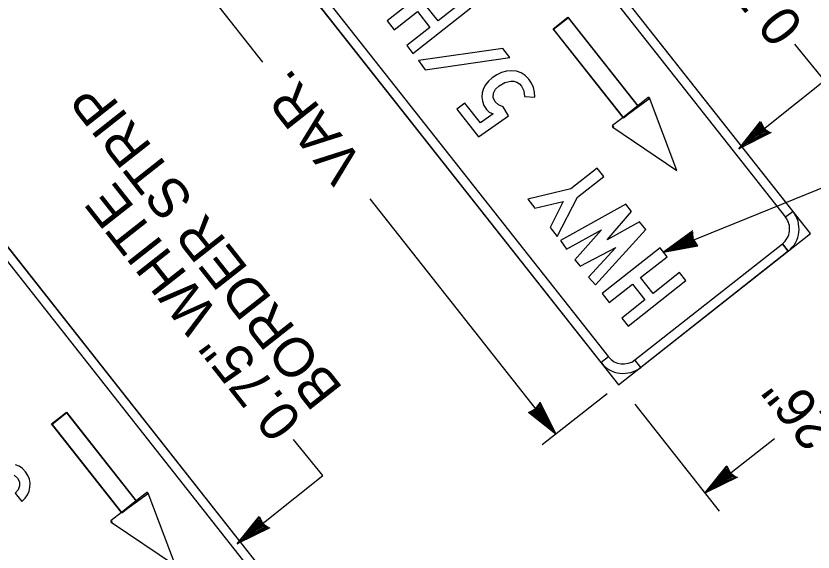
# Model space of a CAD drawing. Extents: x 672239 to 673995, y 1673540 to 1675195.
# Drawn here: x 672425.9 to 672510.8, y 1674938.1 to 1674995.2 of the extents above; entities that cross this region are included whole.
import ezdxf

# ---------------------------------------------------------------- set-up
doc = ezdxf.new("R2010")
doc.units = 0
doc.layers.add('C-ALGN-SYMB', color=7, linetype='Continuous')
doc.layers.add('C-ANNO-SYMB', color=7, linetype='Continuous')

msp = doc.modelspace()

# ---------------------------------------------------------------- linework, layer by layer
at = {"layer": 'C-ALGN-SYMB'}
for p, q in [((672452.225, 1674990.264), (672431.41, 1675016.666)), ((672502.851, 1674981.07), (672505.171, 1674983.98)), ((672503.069, 1674981.306), (672505.153, 1674983.832)), ((672503.42, 1674981.582), (672505.15, 1674983.663)), ((672503.639, 1674981.682), (672505.193, 1674983.398)), ((672503.71, 1674981.806), (672505.152, 1674983.532)), ((672505.15, 1674983.663), (672505.288, 1674983.403)), ((672505.152, 1674983.532), (672505.833, 1674982.834)), ((672505.153, 1674983.832), (672505.494, 1674983.267)), ((672505.171, 1674983.98), (672505.564, 1674983.221)), ((672505.193, 1674983.398), (672505.654, 1674982.892)), ((672505.288, 1674983.403), (672505.833, 1674982.834)), ((672506.312, 1674982.776), (672502.851, 1674981.07)), ((672505.954, 1674982.762), (672503.111, 1674981.338)), ((672506.12, 1674982.723), (672503.272, 1674981.43)), ((672505.833, 1674982.834), (672503.639, 1674981.682)), ((672505.833, 1674982.834), (672503.71, 1674981.806)), ((672504.144, 1674982.145), (672505.138, 1674983.254)), ((672505.654, 1674982.892), (672504.144, 1674982.145)), ((672504.531, 1674982.414), (672505.103, 1674983.127)), ((672505.491, 1674982.932), (672504.531, 1674982.414)), ((672505.196, 1674983.266), (672504.691, 1674982.508)), ((672504.867, 1674982.71), (672505.133, 1674983.05)), ((672505.384, 1674982.981), (672504.867, 1674982.71)), ((672505.103, 1674983.127), (672505.384, 1674982.981)), ((672505.133, 1674983.05), (672505.215, 1674982.985)), ((672505.138, 1674983.254), (672505.491, 1674982.932)), ((672505.572, 1674982.996), (672505.196, 1674983.266)), ((672505.215, 1674982.985), (672505.572, 1674982.996)), ((672505.494, 1674983.267), (672506.165, 1674982.794)), ((672505.564, 1674983.221), (672505.805, 1674982.911)), ((672505.805, 1674982.911), (672506.12, 1674982.723)), ((672506.165, 1674982.794), (672505.946, 1674982.857)), ((672505.946, 1674982.857), (672505.954, 1674982.762)), ((672504.691, 1674982.508), (672504.437, 1674982.407)), ((672483.386, 1674950.667), (672463.624, 1674975.735)), ((672497.974, 1674972.305), (672494.854, 1674970.035)), ((672497.795, 1674971.995), (672495.212, 1674970.141)), ((672497.838, 1674972.159), (672495.368, 1674970.24)), ((672497.802, 1674971.854), (672495.762, 1674970.448)), ((672497.802, 1674971.854), (672495.905, 1674970.454)), ((672497.771, 1674971.668), (672496.407, 1674970.68)), ((672497.648, 1674971.237), (672497.824, 1674971.548)), ((672498.004, 1674971.025), (672497.771, 1674971.668)), ((672497.875, 1674971.943), (672497.795, 1674971.995)), ((672498.053, 1674971.107), (672497.802, 1674971.854)), ((672498.103, 1674970.926), (672497.802, 1674971.854)), ((672497.824, 1674971.548), (672497.889, 1674971.089)), ((672497.858, 1674971.793), (672497.838, 1674972.159)), ((672498.02, 1674971.435), (672497.858, 1674971.793)), ((672497.921, 1674972.166), (672497.875, 1674971.943)), ((672498.028, 1674971.353), (672497.921, 1674972.166)), ((672494.854, 1674970.035), (672498.509, 1674970.735)), ((672495.164, 1674970.118), (672498.369, 1674970.788)), ((672495.334, 1674970.31), (672496.083, 1674970.82)), ((672495.572, 1674970.301), (672498.219, 1674970.864)), ((672496.083, 1674970.82), (672495.572, 1674970.301)), ((672495.762, 1674970.448), (672498.004, 1674971.025)), ((672495.905, 1674970.454), (672498.103, 1674970.926)), ((672496.299, 1674970.659), (672496.686, 1674970.948)), ((672496.776, 1674970.817), (672496.299, 1674970.659)), ((672496.407, 1674970.68), (672497.851, 1674971.043)), ((672496.983, 1674970.994), (672496.776, 1674970.817)), ((672497.73, 1674971.506), (672496.825, 1674970.897)), ((672496.825, 1674970.897), (672497.722, 1674971.071)), ((672497.889, 1674971.089), (672496.983, 1674970.994)), ((672497.724, 1674971.388), (672497.243, 1674971.056)), ((672497.243, 1674971.056), (672497.668, 1674971.134)), ((672497.668, 1674971.134), (672497.648, 1674971.237)), ((672497.722, 1674971.071), (672497.724, 1674971.388)), ((672497.851, 1674971.043), (672497.73, 1674971.506)), ((672498.509, 1674970.735), (672498.02, 1674971.435)), ((672498.369, 1674970.788), (672498.028, 1674971.353)), ((672498.219, 1674970.864), (672498.053, 1674971.107)), ((672495.368, 1674970.24), (672495.164, 1674970.118)), ((672495.212, 1674970.141), (672495.334, 1674970.31)), ((672488.846, 1674954.972), (672481.942, 1674949.529)), ((672481.191, 1674953.311), (672481.664, 1674953.982)), ((672481.547, 1674953.622), (672481.735, 1674953.937)), ((672481.664, 1674953.982), (672481.601, 1674953.763)), ((672481.601, 1674953.763), (672481.696, 1674953.771)), ((672481.682, 1674954.129), (672483.386, 1674950.667)), ((672481.696, 1674953.771), (672483.118, 1674950.927)), ((672481.735, 1674953.937), (672483.026, 1674951.088)), ((672491.789, 1674953.846), (672500.745, 1674942.486)), ((672480.477, 1674952.989), (672481.237, 1674953.381)), ((672483.386, 1674950.667), (672480.477, 1674952.989)), ((672480.626, 1674952.97), (672481.191, 1674953.311)), ((672483.15, 1674950.885), (672480.626, 1674952.97)), ((672480.794, 1674952.968), (672481.054, 1674953.106)), ((672482.874, 1674951.236), (672480.794, 1674952.968)), ((672480.926, 1674952.969), (672481.624, 1674953.65)), ((672482.651, 1674951.527), (672480.926, 1674952.969)), ((672481.054, 1674953.106), (672481.624, 1674953.65)), ((672481.06, 1674953.011), (672481.566, 1674953.471)), ((672482.775, 1674951.455), (672481.06, 1674953.011)), ((672481.462, 1674953.389), (672481.191, 1674953.014)), ((672481.191, 1674953.014), (672481.949, 1674952.508)), ((672481.204, 1674952.955), (672481.526, 1674953.308)), ((672482.312, 1674951.961), (672481.204, 1674952.955)), ((672481.237, 1674953.381), (672481.547, 1674953.622)), ((672481.331, 1674952.92), (672481.477, 1674953.201)), ((672482.043, 1674952.348), (672481.331, 1674952.92)), ((672481.408, 1674952.95), (672481.473, 1674953.032)), ((672481.747, 1674952.684), (672481.408, 1674952.95)), ((672481.473, 1674953.032), (672481.462, 1674953.389)), ((672481.477, 1674953.201), (672481.747, 1674952.684)), ((672481.526, 1674953.308), (672482.043, 1674952.348)), ((672481.566, 1674953.471), (672482.312, 1674951.961)), ((672481.624, 1674953.65), (672482.651, 1674951.527)), ((672481.624, 1674953.65), (672482.775, 1674951.455)), ((672481.949, 1674952.508), (672482.05, 1674952.254)), ((672482.05, 1674952.254), (672482.397, 1674951.893)), ((672482.397, 1674951.893), (672482.19, 1674952.328)), ((672483.089, 1674951.135), (672482.664, 1674951.934)), ((672482.664, 1674951.934), (672482.874, 1674951.236)), ((672483.026, 1674951.088), (672483.15, 1674950.885)), ((672483.118, 1674950.927), (672483.089, 1674951.135)), ((672499.25, 1674944.382), (672506.639, 1674950.206)), ((672499.25, 1674944.382), (672501.572, 1674947.29)), ((672499.468, 1674944.618), (672501.554, 1674947.142)), ((672499.82, 1674944.893), (672501.551, 1674946.973)), ((672501.551, 1674946.973), (672501.689, 1674946.713)), ((672501.554, 1674947.142), (672501.894, 1674946.576)), ((672501.572, 1674947.29), (672501.964, 1674946.531)), ((672502.712, 1674946.085), (672499.25, 1674944.382)), ((672500.038, 1674944.993), (672501.594, 1674946.708)), ((672502.233, 1674946.143), (672500.038, 1674944.993)), ((672500.11, 1674945.117), (672501.552, 1674946.842)), ((672502.233, 1674946.143), (672500.11, 1674945.117)), ((672500.544, 1674945.456), (672501.538, 1674946.564)), ((672502.054, 1674946.202), (672500.544, 1674945.456)), ((672500.931, 1674945.725), (672501.503, 1674946.437)), ((672501.891, 1674946.242), (672500.931, 1674945.725)), ((672501.597, 1674946.576), (672501.091, 1674945.818)), ((672501.267, 1674946.02), (672501.533, 1674946.36)), ((672501.784, 1674946.291), (672501.267, 1674946.02)), ((672501.503, 1674946.437), (672501.784, 1674946.291)), ((672501.533, 1674946.36), (672501.615, 1674946.295)), ((672501.538, 1674946.564), (672501.891, 1674946.242)), ((672501.552, 1674946.842), (672502.233, 1674946.143)), ((672501.594, 1674946.708), (672502.054, 1674946.202)), ((672501.972, 1674946.305), (672501.597, 1674946.576)), ((672501.615, 1674946.295), (672501.972, 1674946.305)), ((672501.689, 1674946.713), (672502.233, 1674946.143)), ((672501.894, 1674946.576), (672502.565, 1674946.103)), ((672501.964, 1674946.531), (672502.205, 1674946.221)), ((672502.205, 1674946.221), (672502.52, 1674946.033)), ((672502.565, 1674946.103), (672502.346, 1674946.167)), ((672502.346, 1674946.167), (672502.354, 1674946.071)), ((672502.354, 1674946.071), (672499.51, 1674944.649)), ((672502.52, 1674946.033), (672499.671, 1674944.741)), ((672500.837, 1674945.718), (672500.476, 1674945.37)), ((672500.476, 1674945.37), (672500.911, 1674945.578)), ((672501.091, 1674945.818), (672500.837, 1674945.718)), ((672499.671, 1674944.741), (672499.468, 1674944.618)), ((672499.51, 1674944.649), (672499.718, 1674944.679)), ((672499.718, 1674944.679), (672500.517, 1674945.103)), ((672500.517, 1674945.103), (672499.82, 1674944.893)), ((672449.489, 1674939.002), (672451.808, 1674941.912)), ((672451.808, 1674941.912), (672452.201, 1674941.152)), ((672449.706, 1674939.238), (672451.79, 1674941.763)), ((672450.058, 1674939.514), (672451.788, 1674941.595)), ((672450.276, 1674939.614), (672451.831, 1674941.33)), ((672450.348, 1674939.737), (672451.789, 1674941.463)), ((672450.782, 1674940.077), (672451.775, 1674941.185)), ((672451.169, 1674940.346), (672451.74, 1674941.058)), ((672451.834, 1674941.198), (672451.328, 1674940.44)), ((672451.74, 1674941.058), (672452.021, 1674940.913)), ((672451.775, 1674941.185), (672452.129, 1674940.863)), ((672451.788, 1674941.595), (672451.926, 1674941.335)), ((672451.789, 1674941.463), (672452.47, 1674940.765)), ((672451.79, 1674941.763), (672452.131, 1674941.198)), ((672451.831, 1674941.33), (672452.291, 1674940.824)), ((672452.21, 1674940.927), (672451.834, 1674941.198)), ((672451.926, 1674941.335), (672452.47, 1674940.765)), ((672452.131, 1674941.198), (672452.802, 1674940.725)), ((672452.201, 1674941.152), (672452.443, 1674940.843)), ((672452.949, 1674940.707), (672449.489, 1674939.002)), ((672452.591, 1674940.693), (672449.748, 1674939.27)), ((672452.757, 1674940.655), (672449.909, 1674939.362)), ((672452.47, 1674940.765), (672450.276, 1674939.614)), ((672452.47, 1674940.765), (672450.348, 1674939.737)), ((672452.291, 1674940.824), (672450.782, 1674940.077)), ((672451.328, 1674940.44), (672451.075, 1674940.339)), ((672452.129, 1674940.863), (672451.169, 1674940.346)), ((672451.504, 1674940.642), (672451.77, 1674940.981)), ((672452.021, 1674940.913), (672451.504, 1674940.642)), ((672451.77, 1674940.981), (672451.852, 1674940.916)), ((672451.852, 1674940.916), (672452.21, 1674940.927)), ((672452.443, 1674940.843), (672452.757, 1674940.655)), ((672452.802, 1674940.725), (672452.583, 1674940.789)), ((672452.583, 1674940.789), (672452.591, 1674940.693))]:
    msp.add_line(p, q, dxfattribs=at)
for points in [[(672502.851, 1674981.07), (672511.964, 1674988.331), (672508.827, 1674992.187)], [(672494.854, 1674970.035), (672517.567, 1674979.294), (672518.79, 1674977.743)], [(672449.489, 1674939.002), (672458.601, 1674946.262), (672455.464, 1674950.118)]]:
    msp.add_lwpolyline(points, dxfattribs=at)
at = {"layer": 'C-ANNO-SYMB'}
for p, q in [((672510.477, 1674972.024), (672458.472, 1675037.99)), ((672508.619, 1674974.38), (672460.329, 1675035.634)), ((672459.544, 1675035.015), (672507.834, 1674973.761)), ((672438.054, 1675021.894), (672490.058, 1674955.928)), ((672440.697, 1675020.157), (672488.986, 1674958.903)), ((672488.201, 1674958.284), (672439.911, 1675019.538)), ((672457.114, 1674929.956), (672405.109, 1674995.922)), ((672483.102, 1674993.827), (672484.672, 1674995.065)), ((672484.715, 1674995.01), (672483.145, 1674993.772)), ((672484.672, 1674995.065), (672484.672, 1674995.065)), ((672484.672, 1674995.065), (672484.672, 1674995.065)), ((672484.672, 1674995.065), (672492.101, 1674985.641)), ((672492.144, 1674985.586), (672484.715, 1674995.01)), ((672490.531, 1674984.403), (672483.102, 1674993.827)), ((672483.145, 1674993.772), (672483.145, 1674993.772)), ((672483.145, 1674993.772), (672483.145, 1674993.772)), ((672483.145, 1674993.772), (672490.574, 1674984.348)), ((672406.181, 1674992.947), (672454.471, 1674931.693)), ((672455.257, 1674932.312), (672406.967, 1674993.566)), ((672493.399, 1674986.411), (672490.574, 1674984.348)), ((672493.201, 1674986.508), (672492.101, 1674985.641)), ((672493.263, 1674986.429), (672493.201, 1674986.508)), ((672493.201, 1674986.508), (672493.263, 1674986.429)), ((672493.244, 1674986.453), (672493.306, 1674986.375)), ((672493.306, 1674986.375), (672493.244, 1674986.453)), ((672493.356, 1674986.466), (672493.263, 1674986.429)), ((672493.263, 1674986.429), (672493.356, 1674986.466)), ((672493.306, 1674986.375), (672493.399, 1674986.411)), ((672493.306, 1674986.375), (672493.399, 1674986.411)), ((672496.269, 1674978.739), (672493.356, 1674986.466)), ((672490.531, 1674984.403), (672492.101, 1674985.641)), ((672490.531, 1674984.403), (672492.101, 1674985.641)), ((672492.101, 1674985.641), (672490.531, 1674984.403)), ((672492.144, 1674985.586), (672490.574, 1674984.348)), ((672490.574, 1674984.348), (672492.144, 1674985.586)), ((672490.531, 1674984.403), (672489.431, 1674983.536)), ((672489.431, 1674983.536), (672489.493, 1674983.458)), ((672489.493, 1674983.458), (672489.431, 1674983.536)), ((672489.493, 1674983.458), (672489.436, 1674983.376)), ((672489.436, 1674983.376), (672489.493, 1674983.458)), ((672489.536, 1674983.403), (672489.474, 1674983.482)), ((672489.474, 1674983.482), (672489.536, 1674983.403)), ((672489.479, 1674983.321), (672489.536, 1674983.403)), ((672489.536, 1674983.403), (672489.479, 1674983.321)), ((672489.436, 1674983.376), (672496.269, 1674978.739)), ((672496.269, 1674978.739), (672496.269, 1674978.739)), ((672496.269, 1674978.739), (672496.269, 1674978.739)), ((672496.312, 1674978.685), (672496.312, 1674978.685)), ((672496.312, 1674978.685), (672496.312, 1674978.685)), ((672508.619, 1674974.38), (672507.834, 1674973.761)), ((672508.619, 1674974.38), (672507.834, 1674973.761)), ((672507.834, 1674973.761), (672507.834, 1674973.761)), ((672507.834, 1674973.761), (672507.834, 1674973.761)), ((672490.058, 1674955.928), (672510.477, 1674972.024)), ((672510.477, 1674972.024), (672510.477, 1674972.024)), ((672510.477, 1674972.024), (672510.477, 1674972.024)), ((672491.795, 1674958.57), (672507.502, 1674970.952)), ((672507.502, 1674970.952), (672508.121, 1674970.167)), ((672508.121, 1674970.167), (672507.502, 1674970.952)), ((672508.121, 1674970.167), (672492.414, 1674957.785)), ((672488.986, 1674958.903), (672488.201, 1674958.284)), ((672488.986, 1674958.903), (672488.201, 1674958.284)), ((672492.414, 1674957.785), (672491.795, 1674958.57)), ((672491.795, 1674958.57), (672491.795, 1674958.57)), ((672491.795, 1674958.57), (672491.795, 1674958.57)), ((672492.414, 1674957.785), (672491.795, 1674958.57)), ((672429.739, 1674951.758), (672431.31, 1674952.996)), ((672431.353, 1674952.942), (672429.782, 1674951.704)), ((672431.31, 1674952.996), (672431.31, 1674952.996)), ((672431.31, 1674952.996), (672431.31, 1674952.996)), ((672431.31, 1674952.996), (672438.739, 1674943.573)), ((672438.782, 1674943.518), (672431.353, 1674952.942)), ((672437.168, 1674942.334), (672429.739, 1674951.758)), ((672429.782, 1674951.704), (672429.782, 1674951.704)), ((672429.782, 1674951.704), (672429.782, 1674951.704)), ((672429.782, 1674951.704), (672437.211, 1674942.28)), ((672439.838, 1674944.439), (672438.739, 1674943.573)), ((672439.9, 1674944.361), (672439.838, 1674944.439)), ((672439.838, 1674944.439), (672439.9, 1674944.361)), ((672439.881, 1674944.385), (672439.943, 1674944.306)), ((672439.943, 1674944.306), (672439.881, 1674944.385)), ((672439.993, 1674944.397), (672439.9, 1674944.361)), ((672439.9, 1674944.361), (672439.993, 1674944.397)), ((672442.906, 1674936.671), (672439.993, 1674944.397)), ((672437.168, 1674942.334), (672438.739, 1674943.573)), ((672437.168, 1674942.334), (672438.739, 1674943.573)), ((672438.739, 1674943.573), (672437.168, 1674942.334)), ((672440.036, 1674944.343), (672437.211, 1674942.28)), ((672439.943, 1674944.306), (672440.036, 1674944.343)), ((672439.943, 1674944.306), (672440.036, 1674944.343)), ((672438.782, 1674943.518), (672437.211, 1674942.28)), ((672437.211, 1674942.28), (672438.782, 1674943.518)), ((672437.168, 1674942.334), (672436.069, 1674941.468)), ((672436.069, 1674941.468), (672436.131, 1674941.389)), ((672436.131, 1674941.389), (672436.069, 1674941.468)), ((672436.131, 1674941.389), (672436.074, 1674941.307)), ((672436.074, 1674941.307), (672436.131, 1674941.389)), ((672436.074, 1674941.307), (672442.906, 1674936.671)), ((672436.174, 1674941.335), (672436.112, 1674941.413)), ((672436.112, 1674941.413), (672436.174, 1674941.335)), ((672436.117, 1674941.253), (672436.174, 1674941.335)), ((672436.174, 1674941.335), (672436.117, 1674941.253))]:
    msp.add_line(p, q, dxfattribs=at)
for points in [[(672474.343, 1674996.053), (672473.677, 1674996.898), (672470.849, 1674994.669), (672469.516, 1674996.36), (672472.343, 1674998.59), (672471.601, 1674999.531), (672465.439, 1674994.674), (672466.182, 1674993.732), (672468.653, 1674995.68), (672469.986, 1674993.988), (672467.516, 1674992.04), (672468.182, 1674991.195)], [(672478.503, 1674990.775), (672477.749, 1674991.732), (672468.766, 1674990.454), (672469.47, 1674989.457)], [(672481.148, 1674986.544), (672481.114, 1674987.083), (672480.996, 1674987.583), (672480.796, 1674988.045), (672480.514, 1674988.472), (672480.129, 1674988.872), (672479.689, 1674989.156), (672479.195, 1674989.324), (672478.644, 1674989.375), (672478.119, 1674989.326), (672477.608, 1674989.183), (672477.111, 1674988.947), (672476.623, 1674988.618), (672476.225, 1674988.258), (672475.91, 1674987.872), (672475.684, 1674987.465), (672475.544, 1674987.032), (672475.502, 1674986.565), (672475.564, 1674986.111), (672475.737, 1674985.666), (672476.014, 1674985.237), (672476.302, 1674984.973), (672476.7, 1674984.77), (672475.363, 1674983.826), (672473.707, 1674985.927), (672472.861, 1674985.26), (672475.173, 1674982.327), (672478.336, 1674984.577), (672477.774, 1674985.516), (672477.301, 1674985.724), (672476.932, 1674986.06), (672476.718, 1674986.51), (672476.754, 1674986.988), (672476.977, 1674987.397), (672477.356, 1674987.775), (672477.961, 1674988.133), (672478.581, 1674988.266), (672478.92, 1674988.244), (672479.224, 1674988.142), (672479.501, 1674987.966), (672479.742, 1674987.713), (672479.988, 1674987.226), (672480.04, 1674986.629)], [(672481.159, 1674974.734), (672484.159, 1674975.437), (672482.792, 1674972.663), (672483.536, 1674971.72), (672485.695, 1674975.911), (672488.487, 1674978.111), (672487.786, 1674979), (672484.995, 1674976.8), (672480.4, 1674975.697)], [(672492.95, 1674972.45), (672492.302, 1674973.273), (672488.832, 1674971.358), (672491.426, 1674974.383), (672490.826, 1674975.144), (672483.875, 1674971.289), (672484.509, 1674970.381), (672488.251, 1674972.443), (672485.411, 1674969.237), (672485.959, 1674968.542), (672489.754, 1674970.537), (672486.856, 1674967.404), (672487.597, 1674966.568)], [(672497.225, 1674967.028), (672496.559, 1674967.873), (672493.731, 1674965.644), (672492.398, 1674967.335), (672495.225, 1674969.564), (672494.483, 1674970.506), (672488.321, 1674965.649), (672489.064, 1674964.707), (672491.535, 1674966.655), (672492.868, 1674964.963), (672490.398, 1674963.015), (672491.064, 1674962.17)]]:
    msp.add_lwpolyline(points, close=True, dxfattribs=at)
msp.add_lwpolyline([(672425.74, 1674946.313), (672426.106, 1674945.992), (672426.305, 1674945.604), (672426.319, 1674945.171), (672426.171, 1674944.749), (672425.875, 1674944.39), (672426.566, 1674943.514), (672426.906, 1674943.837), (672427.161, 1674944.197), (672427.338, 1674944.588), (672427.433, 1674945.015), (672427.449, 1674945.449), (672427.372, 1674945.87), (672427.208, 1674946.27), (672426.951, 1674946.658), (672426.637, 1674946.995), (672426.282, 1674947.248), (672425.895, 1674947.417)], dxfattribs=at)
for centre, radius, start, end in [((672493.263, 1674986.429), 0.1, 21.14769, 128.25069), ((672489.493, 1674983.458), 0.1, 128.25069, 235.35312), ((672506.263, 1674972.523), 3, 308.25039, 38.2506), ((672506.263, 1674972.523), 2, 308.25039, 38.2506), ((672490.557, 1674960.141), 2, 218.25075, 308.25039), ((672490.557, 1674960.141), 3, 218.25075, 308.25039), ((672439.9, 1674944.361), 0.1, 21.14769, 128.25069), ((672436.131, 1674941.389), 0.1, 128.25069, 235.35312)]:
    msp.add_arc(centre, radius, start, end, dxfattribs=at)

# ---------------------------------------------------------------- texts
at = {"layer": 'C-ALGN-SYMB'}
for s, p in [('0.75" WHITE ', (672509.897, 1674994.199)), ('VAR.', (672463.072, 1674979.485)), ('BORDER STRIP', (672460.828, 1674955.515)), ('0.75" WHITE ', (672456.534, 1674952.13)), ('26"', (672513.505, 1674951.106))]:
    msp.add_text(s, height=4.2, rotation=128.25054, dxfattribs=at).set_placement(p)

doc.saveas('drawing.dxf')
